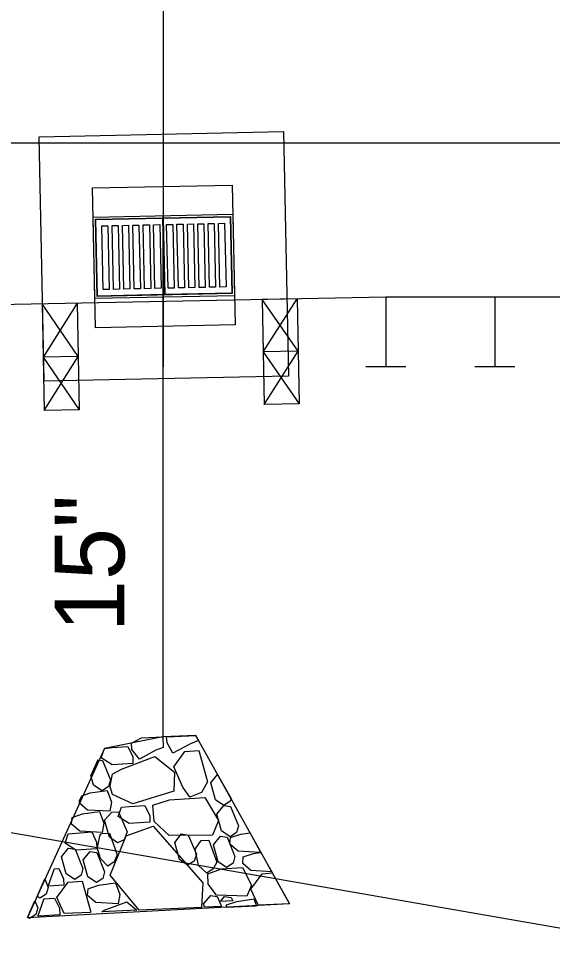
# Model space of a CAD drawing. Extents: x -20 to 509, y -659 to 21.
# Drawn here: x 65.09 to 80.39, y -403.71 to -377.49 of the extents above; entities that cross this region are included whole.
import ezdxf

# ---------------------------------------------------------------- set-up
doc = ezdxf.new("R2010")
doc.units = 0
for name, color, linetype in [('Default', 7, 'Continuous'), ('Exist Vegetation Woods Line', 7, 'Continuous'), ('Prop EOT', 7, 'Continuous'), ('Sup Concrete Girder Lines', 7, 'Continuous'), ('Text', 7, 'Continuous')]:
    doc.layers.add(name, color=color, linetype=linetype)

msp = doc.modelspace()

# ---------------------------------------------------------------- linework, layer by layer
at = {"layer": 'Default'}
for p, q in [((69.229, -383.139), (69.227, -398.052)), ((69.229, -383.139), (69.229, -383.139)), ((67.255, -384.348), (67.255, -384.348)), ((69.254, -384.305), (69.254, -384.305)), ((71.254, -384.262), (71.254, -384.262)), ((75.61, -385.469), (28.868, -386.404)), ((65.768, -385.666), (65.829, -388.718)), ((66.798, -387.172), (65.768, -385.666)), ((66.768, -385.646), (65.798, -387.192)), ((66.768, -385.646), (66.829, -388.698)), ((69.279, -385.471), (69.279, -385.471)), ((73.068, -385.52), (72.068, -385.54)), ((72.068, -385.54), (72.128, -388.539)), ((72.068, -385.54), (72.098, -387.04)), ((73.098, -387.02), (72.068, -385.54)), ((72.098, -387.04), (73.068, -385.52)), ((73.068, -385.52), (73.128, -388.519)), ((75.61, -385.469), (75.61, -387.469)), ((94.36, -385.469), (75.61, -385.469)), ((78.735, -385.469), (78.735, -387.469)), ((66.798, -387.172), (65.798, -387.192)), ((65.798, -387.192), (66.829, -388.698)), ((65.829, -388.718), (66.798, -387.172)), ((73.098, -387.02), (72.098, -387.04)), ((72.098, -387.04), (73.128, -388.519)), ((72.128, -388.539), (73.098, -387.02)), ((76.183, -387.469), (75.037, -387.469)), ((79.308, -387.469), (78.162, -387.469)), ((73.128, -388.519), (72.128, -388.539)), ((66.829, -388.698), (65.829, -388.718)), ((68.611, -398.08), (69.227, -398.052)), ((69.227, -398.052), (69.227, -398.052)), ((69.326, -398.048), (70.174, -398.011)), ((70.241, -398.131), (70.174, -398.011)), ((67.363, -398.709), (67.165, -399.153)), ((67.772, -399.119), (67.703, -399.458)), ((70.795, -399.128), (71.179, -399.819)), ((66.839, -399.883), (66.904, -399.739)), ((72.02, -401.343), (71.722, -400.796)), ((67.409, -400.898), (67.343, -401.22)), ((65.939, -402.327), (66.119, -401.823)), ((65.622, -402.618), (65.841, -402.116)), ((72.359, -401.947), (72.852, -402.826)), ((65.816, -402.685), (65.645, -403.172)), ((65.351, -403.216), (65.563, -402.74)), ((70.33, -402.932), (68.55, -403.01)), ((70.901, -402.908), (70.419, -402.929)), ((71.225, -402.743), (70.877, -402.758)), ((71.045, -402.926), (71.909, -402.888)), ((71.955, -402.862), (72.852, -402.823)), ((67.158, -403.073), (66.396, -403.106)), ((68.484, -403.015), (67.482, -403.059))]:
    msp.add_line(p, q, dxfattribs=at)
for points in [[(65.68, -380.881), (72.678, -380.731), (72.828, -387.729), (65.83, -387.879)], [(67.212, -382.348), (71.211, -382.263), (71.297, -386.262), (67.297, -386.348)]]:
    msp.add_lwpolyline(points, close=True, dxfattribs=at)
for points in [[(67.23, -383.182), (71.229, -383.096), (71.279, -385.429), (67.28, -385.514), (67.23, -383.182)], [(67.293, -383.243), (71.167, -383.16), (71.215, -385.367), (67.341, -385.451), (67.293, -383.243)], [(67.304, -383.253), (69.22, -383.212), (69.267, -385.399), (67.351, -385.44), (67.304, -383.253)], [(69.241, -383.211), (71.157, -383.17), (71.204, -385.357), (69.288, -385.398), (69.241, -383.211)], [(67.475, -383.432), (67.652, -383.428), (67.691, -385.25), (67.514, -385.254), (67.475, -383.432)], [(67.771, -383.425), (67.948, -383.421), (67.988, -385.244), (67.81, -385.248), (67.771, -383.425)], [(68.068, -383.419), (68.245, -383.415), (68.284, -385.238), (68.107, -385.241), (68.068, -383.419)], [(68.365, -383.412), (68.542, -383.409), (68.581, -385.231), (68.404, -385.235), (68.365, -383.412)], [(68.662, -383.406), (68.839, -383.402), (68.878, -385.225), (68.701, -385.229), (68.662, -383.406)], [(68.959, -383.4), (69.136, -383.396), (69.175, -385.218), (68.998, -385.222), (68.959, -383.4)], [(69.333, -383.392), (69.51, -383.388), (69.55, -385.21), (69.373, -385.214), (69.333, -383.392)], [(69.63, -383.385), (69.807, -383.382), (69.846, -385.204), (69.669, -385.208), (69.63, -383.385)], [(69.927, -383.379), (70.104, -383.375), (70.143, -385.198), (69.966, -385.201), (69.927, -383.379)], [(70.224, -383.373), (70.401, -383.369), (70.44, -385.191), (70.263, -385.195), (70.224, -383.373)], [(70.521, -383.366), (70.698, -383.362), (70.737, -385.185), (70.56, -385.189), (70.521, -383.366)], [(70.817, -383.36), (70.994, -383.356), (71.034, -385.179), (70.856, -385.182), (70.817, -383.36)], [(69.238, -398.352), (69.029, -398.436), (68.552, -398.694), (68.34, -398.416), (68.332, -398.228), (68.611, -398.08)], [(69.225, -398.053), (69.238, -398.352)], [(70.243, -398.158), (70.022, -398.255), (69.508, -398.515), (69.345, -398.222), (69.326, -398.048)], [(70.241, -398.131), (70.243, -398.158)], [(67.55, -398.384), (67.774, -398.361), (68.223, -398.329), (68.361, -398.624), (68.369, -398.811), (67.771, -398.85), (67.462, -398.65), (67.55, -398.384)], [(70.001, -399.782), (69.801, -399.491), (69.538, -398.914), (69.857, -398.475), (70.256, -398.445), (70.507, -399.335), (70.333, -399.643), (70.001, -399.782)], [(67.363, -398.709), (67.499, -398.731), (67.724, -399.284), (67.669, -399.474), (67.487, -399.594)], [(67.772, -399.119), (68.039, -398.979), (68.999, -398.612), (69.557, -399.063), (69.543, -399.602), (68.37, -399.966), (67.783, -399.704), (67.703, -399.458)], [(67.487, -399.594), (67.242, -399.43), (67.165, -399.153)], [(70.975, -400.017), (70.73, -399.852), (70.596, -399.37), (70.795, -399.128)], [(66.904, -399.739), (67.146, -399.656), (67.631, -399.585), (67.758, -399.917), (67.707, -400.182), (67.068, -400.148), (66.834, -399.945), (66.839, -399.883)], [(68.935, -400.004), (69.416, -399.858), (70.427, -399.789), (70.818, -400.447), (70.649, -400.868), (69.411, -400.871), (68.981, -400.477), (68.935, -400.004)], [(71.179, -399.819), (71.157, -399.896), (70.975, -400.017)], [(68.037, -400.068), (68.261, -400.046), (68.71, -400.014), (68.848, -400.308), (68.856, -400.495), (68.257, -400.534), (67.948, -400.335), (68.037, -400.068)], [(71.151, -400.91), (70.907, -400.745), (70.773, -400.263), (70.975, -400.017), (71.164, -400.046), (71.388, -400.599), (71.334, -400.789), (71.151, -400.91)], [(66.628, -400.359), (66.924, -400.258), (67.409, -400.187), (67.536, -400.519), (67.485, -400.784), (66.846, -400.75), (66.612, -400.547), (66.628, -400.359)], [(67.931, -401.086), (67.699, -400.921), (67.553, -400.44), (67.768, -400.205), (67.955, -400.197), (68.205, -400.774), (68.115, -401.003), (67.931, -401.086)], [(68.55, -403.01), (67.721, -402.009), (68.173, -400.888), (68.949, -400.604), (70.371, -402.231), (70.33, -402.933)], [(66.516, -400.827), (66.74, -400.805), (67.189, -400.773), (67.327, -401.067), (67.335, -401.254), (66.736, -401.293), (66.427, -401.094), (66.516, -400.827)], [(67.409, -400.898), (67.469, -400.819), (67.694, -400.809), (67.921, -401.424), (67.83, -401.629), (67.647, -401.749)], [(69.936, -401.724), (69.703, -401.559), (69.57, -401.077), (69.759, -400.831), (69.948, -400.861), (70.185, -401.413), (70.118, -401.604), (69.936, -401.724)], [(71.16, -400.935), (71.456, -400.834), (71.722, -400.796)], [(70.484, -401.951), (70.249, -401.736), (70.153, -401.264), (70.318, -401.02), (70.543, -401.01), (70.77, -401.638), (70.666, -401.83), (70.484, -401.951)], [(71.052, -401.788), (70.807, -401.624), (70.674, -401.142), (70.876, -400.895), (71.065, -400.924), (71.289, -401.478), (71.235, -401.668), (71.052, -401.788)], [(72.02, -401.343), (72.017, -401.361), (71.378, -401.326), (71.144, -401.123), (71.16, -400.935)], [(66.7, -402.132), (66.455, -401.968), (66.322, -401.485), (66.524, -401.239), (66.712, -401.268), (66.937, -401.821), (66.883, -402.011), (66.7, -402.132)], [(67.321, -402.221), (67.076, -402.056), (66.942, -401.574), (67.144, -401.328), (67.333, -401.357), (67.558, -401.91), (67.503, -402.1), (67.321, -402.221)], [(67.647, -401.749), (67.438, -401.533), (67.343, -401.22)], [(71.53, -401.489), (71.826, -401.389), (72.028, -401.359)], [(72.027, -401.359), (72.028, -401.359), (72.342, -401.912)], [(72.344, -401.912), (71.747, -401.88), (71.513, -401.678), (71.53, -401.489)], [(66.117, -401.826), (66.242, -401.817), (66.38, -402.111), (66.388, -402.299), (65.941, -402.327)], [(70.51, -401.975), (70.904, -401.832), (71.503, -401.794), (71.762, -402.295), (71.626, -402.614), (70.761, -402.577), (70.522, -402.262), (70.51, -401.975)], [(65.842, -402.114), (65.942, -402.362), (65.888, -402.552), (65.706, -402.672)], [(66.399, -403.104), (66.192, -402.65), (66.511, -402.211), (66.91, -402.181), (67.162, -403.071)], [(71.955, -402.862), (71.748, -402.408), (72.067, -401.969), (72.361, -401.947)], [(67.087, -402.399), (67.383, -402.299), (67.868, -402.227), (67.995, -402.56), (67.944, -402.825), (67.305, -402.79), (67.071, -402.588), (67.087, -402.399)], [(65.706, -402.672), (65.619, -402.614)], [(65.816, -402.685), (66.126, -402.663), (66.264, -402.957), (66.272, -403.144), (65.673, -403.183), (65.645, -403.172)], [(70.419, -402.929), (70.393, -402.834), (70.595, -402.588), (70.784, -402.617), (70.901, -402.908)], [(70.877, -402.758), (70.993, -402.616), (71.182, -402.645), (71.225, -402.743)], [(71.051, -402.859), (71.347, -402.758), (71.832, -402.687), (71.909, -402.888)], [(65.562, -402.739), (65.645, -402.943), (65.591, -403.133), (65.408, -403.253)], [(67.482, -403.057), (67.527, -403.018), (68.192, -402.776), (68.484, -403.013)], [(71.045, -402.926), (71.051, -402.859)], [(65.408, -403.253), (65.35, -403.214)]]:
    msp.add_lwpolyline(points, dxfattribs=at)
at = {"layer": 'Exist Vegetation Woods Line'}
msp.add_lwpolyline([(-3.076, -404.032), (57.839, -399.571), (85.143, -404.311), (104.903, -414.952)], dxfattribs=at)
at = {"layer": 'Prop EOT'}
msp.add_line((-3.076, -381.052), (237.897, -381.052), dxfattribs=at)
at = {"layer": 'Sup Concrete Girder Lines'}
for p, q in [((69.232, -359.299), (69.227, -398.052)), ((69.229, -383.139), (69.229, -383.139)), ((67.255, -384.348), (67.255, -384.348)), ((69.254, -384.305), (69.254, -384.305)), ((71.254, -384.262), (71.254, -384.262)), ((69.279, -385.471), (69.279, -385.471)), ((69.227, -398.052), (67.55, -398.384)), ((68.611, -398.08), (69.227, -398.052)), ((70.174, -398.011), (69.227, -398.052)), ((69.227, -398.052), (69.227, -398.052)), ((69.326, -398.048), (70.174, -398.011)), ((70.241, -398.131), (70.174, -398.011)), ((72.852, -402.823), (70.174, -398.011)), ((67.55, -398.384), (65.351, -403.216)), ((67.363, -398.709), (67.165, -399.153)), ((67.772, -399.119), (67.703, -399.458)), ((70.795, -399.128), (71.179, -399.819)), ((66.839, -399.883), (66.904, -399.739)), ((72.02, -401.343), (71.722, -400.796)), ((67.409, -400.898), (67.343, -401.22)), ((65.939, -402.327), (66.119, -401.823)), ((65.622, -402.618), (65.841, -402.116)), ((72.359, -401.947), (72.852, -402.826)), ((65.816, -402.685), (65.645, -403.172)), ((65.351, -403.216), (65.563, -402.74)), ((65.351, -403.216), (72.852, -402.823)), ((70.33, -402.932), (68.55, -403.01)), ((70.901, -402.908), (70.419, -402.929)), ((71.225, -402.743), (70.877, -402.758)), ((71.045, -402.926), (71.909, -402.888)), ((71.955, -402.862), (72.852, -402.823)), ((67.158, -403.073), (66.396, -403.106)), ((68.484, -403.015), (67.482, -403.059))]:
    msp.add_line(p, q, dxfattribs=at)
for points in [[(65.68, -380.881), (72.678, -380.731), (72.828, -387.729), (65.83, -387.879)], [(67.212, -382.348), (71.211, -382.263), (71.297, -386.262), (67.297, -386.348)]]:
    msp.add_lwpolyline(points, close=True, dxfattribs=at)
for points in [[(67.23, -383.182), (71.229, -383.096), (71.279, -385.429), (67.28, -385.514), (67.23, -383.182)], [(67.293, -383.243), (71.167, -383.16), (71.215, -385.367), (67.341, -385.451), (67.293, -383.243)], [(67.304, -383.253), (69.22, -383.212), (69.267, -385.399), (67.351, -385.44), (67.304, -383.253)], [(69.241, -383.211), (71.157, -383.17), (71.204, -385.357), (69.288, -385.398), (69.241, -383.211)], [(67.475, -383.432), (67.652, -383.428), (67.691, -385.25), (67.514, -385.254), (67.475, -383.432)], [(67.771, -383.425), (67.948, -383.421), (67.988, -385.244), (67.81, -385.248), (67.771, -383.425)], [(68.068, -383.419), (68.245, -383.415), (68.284, -385.238), (68.107, -385.241), (68.068, -383.419)], [(68.365, -383.412), (68.542, -383.409), (68.581, -385.231), (68.404, -385.235), (68.365, -383.412)], [(68.662, -383.406), (68.839, -383.402), (68.878, -385.225), (68.701, -385.229), (68.662, -383.406)], [(68.959, -383.4), (69.136, -383.396), (69.175, -385.218), (68.998, -385.222), (68.959, -383.4)], [(69.333, -383.392), (69.51, -383.388), (69.55, -385.21), (69.373, -385.214), (69.333, -383.392)], [(69.63, -383.385), (69.807, -383.382), (69.846, -385.204), (69.669, -385.208), (69.63, -383.385)], [(69.927, -383.379), (70.104, -383.375), (70.143, -385.198), (69.966, -385.201), (69.927, -383.379)], [(70.224, -383.373), (70.401, -383.369), (70.44, -385.191), (70.263, -385.195), (70.224, -383.373)], [(70.521, -383.366), (70.698, -383.362), (70.737, -385.185), (70.56, -385.189), (70.521, -383.366)], [(70.817, -383.36), (70.994, -383.356), (71.034, -385.179), (70.856, -385.182), (70.817, -383.36)], [(69.238, -398.352), (69.029, -398.436), (68.552, -398.694), (68.34, -398.416), (68.332, -398.228), (68.611, -398.08)], [(69.225, -398.053), (69.238, -398.352)], [(70.243, -398.158), (70.022, -398.255), (69.508, -398.515), (69.345, -398.222), (69.326, -398.048)], [(70.241, -398.131), (70.243, -398.158)], [(67.55, -398.384), (67.774, -398.361), (68.223, -398.329), (68.361, -398.624), (68.369, -398.811), (67.771, -398.85), (67.462, -398.65), (67.55, -398.384)], [(70.001, -399.782), (69.801, -399.491), (69.538, -398.914), (69.857, -398.475), (70.256, -398.445), (70.507, -399.335), (70.333, -399.643), (70.001, -399.782)], [(67.363, -398.709), (67.499, -398.731), (67.724, -399.284), (67.669, -399.474), (67.487, -399.594)], [(67.772, -399.119), (68.039, -398.979), (68.999, -398.612), (69.557, -399.063), (69.543, -399.602), (68.37, -399.966), (67.783, -399.704), (67.703, -399.458)], [(67.487, -399.594), (67.242, -399.43), (67.165, -399.153)], [(70.975, -400.017), (70.73, -399.852), (70.596, -399.37), (70.795, -399.128)], [(66.904, -399.739), (67.146, -399.656), (67.631, -399.585), (67.758, -399.917), (67.707, -400.182), (67.068, -400.148), (66.834, -399.945), (66.839, -399.883)], [(68.935, -400.004), (69.416, -399.858), (70.427, -399.789), (70.818, -400.447), (70.649, -400.868), (69.411, -400.871), (68.981, -400.477), (68.935, -400.004)], [(71.179, -399.819), (71.157, -399.896), (70.975, -400.017)], [(68.037, -400.068), (68.261, -400.046), (68.71, -400.014), (68.848, -400.308), (68.856, -400.495), (68.257, -400.534), (67.948, -400.335), (68.037, -400.068)], [(71.151, -400.91), (70.907, -400.745), (70.773, -400.263), (70.975, -400.017), (71.164, -400.046), (71.388, -400.599), (71.334, -400.789), (71.151, -400.91)], [(66.628, -400.359), (66.924, -400.258), (67.409, -400.187), (67.536, -400.519), (67.485, -400.784), (66.846, -400.75), (66.612, -400.547), (66.628, -400.359)], [(67.931, -401.086), (67.699, -400.921), (67.553, -400.44), (67.768, -400.205), (67.955, -400.197), (68.205, -400.774), (68.115, -401.003), (67.931, -401.086)], [(68.55, -403.01), (67.721, -402.009), (68.173, -400.888), (68.949, -400.604), (70.371, -402.231), (70.33, -402.933)], [(66.516, -400.827), (66.74, -400.805), (67.189, -400.773), (67.327, -401.067), (67.335, -401.254), (66.736, -401.293), (66.427, -401.094), (66.516, -400.827)], [(67.409, -400.898), (67.469, -400.819), (67.694, -400.809), (67.921, -401.424), (67.83, -401.629), (67.647, -401.749)], [(69.936, -401.724), (69.703, -401.559), (69.57, -401.077), (69.759, -400.831), (69.948, -400.861), (70.185, -401.413), (70.118, -401.604), (69.936, -401.724)], [(71.16, -400.935), (71.456, -400.834), (71.722, -400.796)], [(70.484, -401.951), (70.249, -401.736), (70.153, -401.264), (70.318, -401.02), (70.543, -401.01), (70.77, -401.638), (70.666, -401.83), (70.484, -401.951)], [(71.052, -401.788), (70.807, -401.624), (70.674, -401.142), (70.876, -400.895), (71.065, -400.924), (71.289, -401.478), (71.235, -401.668), (71.052, -401.788)], [(72.02, -401.343), (72.017, -401.361), (71.378, -401.326), (71.144, -401.123), (71.16, -400.935)], [(66.7, -402.132), (66.455, -401.968), (66.322, -401.485), (66.524, -401.239), (66.712, -401.268), (66.937, -401.821), (66.883, -402.011), (66.7, -402.132)], [(67.321, -402.221), (67.076, -402.056), (66.942, -401.574), (67.144, -401.328), (67.333, -401.357), (67.558, -401.91), (67.503, -402.1), (67.321, -402.221)], [(67.647, -401.749), (67.438, -401.533), (67.343, -401.22)], [(71.53, -401.489), (71.826, -401.389), (72.028, -401.359)], [(72.027, -401.359), (72.028, -401.359), (72.342, -401.912)], [(72.344, -401.912), (71.747, -401.88), (71.513, -401.678), (71.53, -401.489)], [(66.117, -401.826), (66.242, -401.817), (66.38, -402.111), (66.388, -402.299), (65.941, -402.327)], [(70.51, -401.975), (70.904, -401.832), (71.503, -401.794), (71.762, -402.295), (71.626, -402.614), (70.761, -402.577), (70.522, -402.262), (70.51, -401.975)], [(65.842, -402.114), (65.942, -402.362), (65.888, -402.552), (65.706, -402.672)], [(66.399, -403.104), (66.192, -402.65), (66.511, -402.211), (66.91, -402.181), (67.162, -403.071)], [(71.955, -402.862), (71.748, -402.408), (72.067, -401.969), (72.361, -401.947)], [(67.087, -402.399), (67.383, -402.299), (67.868, -402.227), (67.995, -402.56), (67.944, -402.825), (67.305, -402.79), (67.071, -402.588), (67.087, -402.399)], [(65.706, -402.672), (65.619, -402.614)], [(65.816, -402.685), (66.126, -402.663), (66.264, -402.957), (66.272, -403.144), (65.673, -403.183), (65.645, -403.172)], [(70.419, -402.929), (70.393, -402.834), (70.595, -402.588), (70.784, -402.617), (70.901, -402.908)], [(70.877, -402.758), (70.993, -402.616), (71.182, -402.645), (71.225, -402.743)], [(71.051, -402.859), (71.347, -402.758), (71.832, -402.687), (71.909, -402.888)], [(65.562, -402.739), (65.645, -402.943), (65.591, -403.133), (65.408, -403.253)], [(67.482, -403.057), (67.527, -403.018), (68.192, -402.776), (68.484, -403.013)], [(71.045, -402.926), (71.051, -402.859)], [(65.408, -403.253), (65.35, -403.214)]]:
    msp.add_lwpolyline(points, dxfattribs=at)

# ---------------------------------------------------------------- texts
at = {"layer": 'Text'}
msp.add_text('15"', height=2, rotation=90, dxfattribs=at).set_placement((68.126, -395.051))

doc.saveas('drawing.dxf')
